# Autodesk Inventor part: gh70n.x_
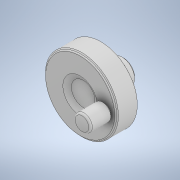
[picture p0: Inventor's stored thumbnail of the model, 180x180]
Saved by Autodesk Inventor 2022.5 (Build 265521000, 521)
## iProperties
Created: 2023-06
Part Number: gh70n.x_
Material: Generic
Document SubType Name: Modeling
Designer: ImaoCorp
Density: 1 g/cm^3
Appearance: Default
Sending System: SOLIDWORKS 2021-2021301
MC: AMD64
MC_MODEL: Intel64 Family 6 Model 60 Stepping 3, GenuineIntel
OS: Windows_NT
FRU: Parasolid Version 32.1, build 255,  1- 1-2021
FORMAT: text
GUISE: transmit
KEY: gh70n
FILE: gh70n.x_t
DATE: Thu Jun 15 16:07:54 2023
Author: ImaoCorp
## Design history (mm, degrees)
feature "Base1"
node "ソリッド1"
